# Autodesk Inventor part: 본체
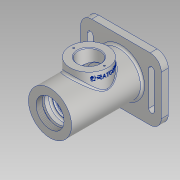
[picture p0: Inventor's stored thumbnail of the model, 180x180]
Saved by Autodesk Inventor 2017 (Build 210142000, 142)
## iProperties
Part Number: 본체
Material: 알루미늄 6061
Document SubType Name: Modeling
Designer: user
Density: 2.7 g/cm^3
Appearance: 알루미늄 - 평지
Mass: 738.134 g
Surface Area: 647.517 cm^2
Volume: 273.383 cm^3
Author: user
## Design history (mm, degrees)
sketch "스케치2"
  geometry: L1 (-58, -45)-(58, -45); L2 (58, -45)-(58, 45); L3 (58, 45)-(-58, 45); L4 (-58, 45)-(-58, -45); L5 (-58, -45)-(58, 45); L6 (58, -45)-(-58, 45); 1 further point
  constraints: 12 end point, 2 midpoint, 2 parallel, 1 horizontal, 1 perpendicular
  dimensions: "d2" = 90 distance of L1.end L2.end; "d3" = 116 distance of L2.end L3.end
extrude "돌출1" new body sketch "스케치2" distance "d4" = 10; taper "d5" = 0 deg
sketch "스케치3"
  geometry: C1 r 35 at (0, 0); 1 further point
  constraints: 1 centre point, 1 coincident
  dimensions: "d6" = 70 diameter of C1
extrude "돌출2" join sketch "스케치3" distance "d7" = 3; taper "d8" = 0 deg
sketch "스케치4"
  geometry: C1 r 31 at (0, 0); 1 further point
  constraints: 1 centre point, 1 coincident
  dimensions: "d9" = 62 diameter of C1
extrude "돌출3" join sketch "스케치4" distance "d10" = 102; taper "d11" = 0 deg
node "작업 평면1"
sketch "스케치5"
  geometry: L1 (31, 112)-(-31, 112) reference; C1 r 27 at (0, 56); 1 further point
  constraints: 1 centre point, 1 vertical alignment
  dimensions: "d13" = 54 diameter of C1; "d14" = 56 distance from line of L1 C1.centre
extrude "돌출4" join sketch "스케치5" stored distance "d16" = 102; taper "d17" = 0 deg
sketch "스케치6"
  geometry: C1 r 31 at (0, 0) reference; 1 further point
  constraints: 1 coincident
hole "구멍1" sketch "스케치6" at (0, 0) diameter "d18" = 40.376; stored, may be unused: countersink angle "d22" = 90 deg, drill point angle "d24" = 0 deg; dims "d19" = 84, "d20" = 4, "d21" = 2, "d23" = 9
sketch "스케치7"
  geometry: L1 (20.188, 103)-(20.188, 112) reference; L2 (20.188, 103)-(-20.188, 103) reference; L3 (-35, -3)-(35, -3) reference; L4 (0, 103)-(0, -3); L5 (0, 103)-(24, 103); L6 (24, 103)-(24, 100); L7 (24, 100)-(20, 100); L8 (20, 100)-(20, 94); L9 (17, 91)-(17.5, 91); L10 (17.5, 91)-(17.5, 87.75); L11 (17.5, 87.75)-(18.5, 87.75); L12 (18.5, 87.75)-(18.5, 86); L13 (18.5, 86)-(17.5, 86); L14 (17.5, 86)-(17.5, 76); L15 (18.5, 75)-(23, 75); L16 (26, 72)-(26, 40); L17 (23, 37)-(18.5, 37); L18 (17.5, 36)-(17.5, 26.3); L19 (17.2, 26)-(16, 26); L20 (16, 26)-(16, 24); L21 (13, 21)-(10, 21); L22 (10, 21)-(10, 18.3); L23 (10, 18.3)-(12.2, 18.3); L24 (12.5, 18)-(12.5, 11.7); L25 (12.904, 11)-(14.022, 11); L26 (16.779, 9.182)-(22, -3); L27 (17.5, 76)-(18.5, 75); L28 (18.5, 37)-(17.5, 36); L29 (12.5, 11.7)-(12.904, 11); A1 r 3 centre (17, 94) between (17, 91) and (20, 94); A2 r 3 centre (23, 72) between (26, 72) and (23, 75); A3 r 3 centre (23, 40) between (23, 37) and (26, 40); A4 r 0.3 centre (17.2, 26.3) between (17.2, 26) and (17.5, 26.3); A5 r 0.3 centre (12.2, 18) between (12.5, 18) and (12.2, 18.3); A6 r 3 centre (14.022, 8) between (16.779, 9.182) and (14.022, 11); A7 r 3 centre (13, 24) between (13, 21) and (16, 24); 11 further points
  constraints: 52 end point, 24 point on line, 17 perpendicular, 14 point on circle, 14 tangent, 7 centre point, 3 equal radius, 2 horizontal, 2 midpoint, 1 vertical
  dimensions: "d25" = 3 distance of L5.end L6.end; "d26" = 9 distance of L7.end point (20, 91); "d27" = 3.25 distance of L9.end L10.end; "d28" = 1.75 distance of L11.end L12.end; "d29" = 11 distance of L13.end point (17.5, 75); "d30" = 38 distance of point (26, 75) point (26, 37); "d31" = 11 distance of point (17.5, 37) point (17.5, 26); "d32" = 5 distance of L19.end point (16, 21); "d33" = 2.7 distance of L21.end L22.end; "d34" = 7.3 distance of point (12.5, 18.3) point (12.5, 11); "d35" = 48 diameter of L6 L4; "d36" = 40 diameter of L8 L4; "d37" = 35 diameter of L10 L4; "d38" = 37 diameter of L12 L4; "d39" = 52 diameter of L16 L4; "d40" = 35 diameter of L18 L4; "d41" = 32 diameter of L20 L4; "d42" = 20 diameter of L22 L4; "d43" = 25 diameter of L24 L4; "d44" = 44 diameter of L26.end L4; "d45" = 3 radius of A1; "d46" = 1 distance of L14.end point (17.5, 75); "d47" = 1 distance of L15.start point (17.5, 75) (= d46); "d48" = 3 radius of A2; "d49" = 1 distance of L17.end point (17.5, 37); "d50" = 1 distance of L18.start point (17.5, 37) (= d49); "d51" = 0.3 radius of A4; "d52" = 0.7 distance of L24.end point (12.5, 11); "d53" = 30 deg angle of L24 L29; "d54" = 3 radius of A6
revolve "회전1" sketch "스케치7" stored, may be unused: angle "d55" = 90 deg
sketch "스케치8"
  geometry: C1 r 27 at (0, 0) reference; C2 r 16 at (0, 0); 1 further point
  constraints: 1 centre point, 1 coincident
  dimensions: "d56" = 32 diameter of C2
extrude "돌출5" cut sketch "스케치8" stored distance "d57" = 102; taper "d58" = 0 deg
sketch "스케치9"
  geometry: C1 r 16 at (0, 0) reference; C2 r 27 at (0, 0) reference; A1 r 22 centre (0, 0) between (-22, 0) and (22, 0); 1 further point
  constraints: 2 horizontal alignment, 2 point on circle, 1 centre point, 1 coincident
  dimensions: "d59" = 44 diameter of A1
hole "구멍2" sketch "스케치9" at (-22, 0), (22, 0) diameter "d60" = 2.459; stored, may be unused: countersink angle "d64" = 90 deg, drill point angle "d66" = 118 deg; dims "d61" = 6, "d62" = 4, "d63" = 2, "d65" = 8
sketch "스케치10"
  geometry: L1 (-44, 25)-(-44, -25); L2 (-48, 25)-(-48, -25); L3 (-40, -25)-(-40, 25); L4 (44, 25)-(44, -25); L5 (40, 25)-(40, -25); L6 (48, -25)-(48, 25); C1 r 31 at (0, 0) reference; A1 r 4 centre (-44, 25) between (-40, 25) and (-48, 25); A2 r 4 centre (-44, -25) between (-48, -25) and (-40, -25); A3 r 4 centre (44, 25) between (48, 25) and (40, 25); A4 r 4 centre (44, -25) between (40, -25) and (48, -25); 2 further points
  constraints: 16 end point, 8 point on circle, 8 tangent, 4 centre point, 3 parallel, 2 horizontal alignment, 2 midpoint, 1 vertical
  dimensions: "d67" = 88 distance of L4.start L1.start; "d68" = 44 horizontal distance of L4.start C1.centre; "d69" = 4 radius of A3; "d70" = 50 distance of L4.start L4.end; "d71" = 50 distance of L1.start L1.end; "d72" = 4 radius of A1
extrude "돌출6" cut sketch "스케치10" distance "d73" = 102; taper "d74" = 0 deg
chamfer "모따기1" distance "d75" = 1; stored, may be unused: second distance "d76" = 2, angle "d77" = 45 deg
fillet "모깎기1" dims "d78" = 3
node "작업 평면2"
sketch "스케치11"
  geometry: L1 (42, 83)-(42, 29) reference; 3 further points
  constraints: 1 horizontal alignment, 1 midpoint, 1 other
  dimensions: "d80" = 8 distance from line of point (34, 56) L1
feature "엠보싱1" sketch "스케치11" dims "d2" = 90, "d3" = 116, "d81" = 0.5, "d82" = 0
fillet "모깎기2" dims "d83" = 16
node "솔리드1"
other parameters: "d12" = 42
